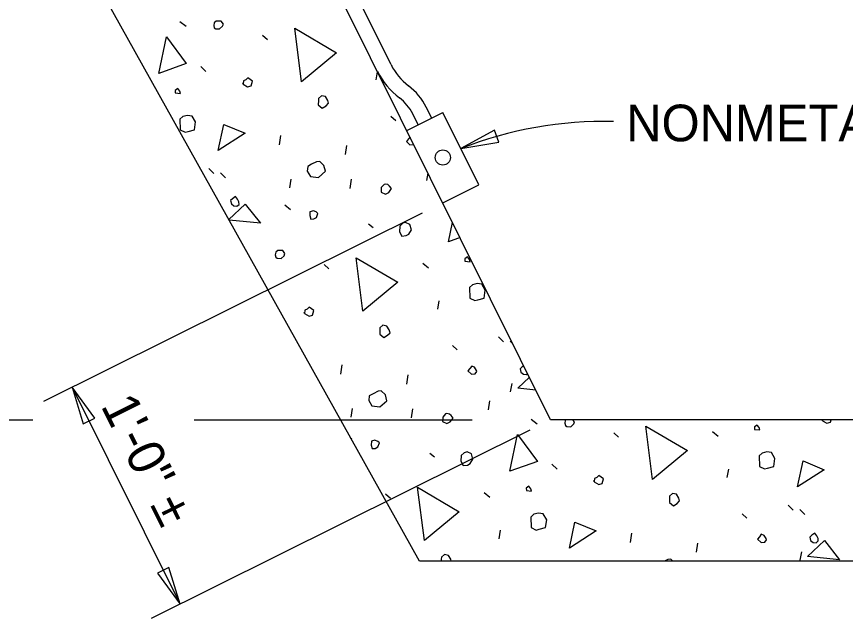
# Model space of a CAD drawing. Extents: x -1660015.2 to -1659984.9, y 2580594.2 to 2580616.7.
# Drawn here: x -1660010.453 to -1660007.032, y 2580605.475 to 2580607.958 of the extents above; entities that cross this region are included whole.
import ezdxf

# ---------------------------------------------------------------- set-up
doc = ezdxf.new("R2010")
doc.units = 0
for name, color, linetype in [('Default', 7, 'Continuous'), ('Miscellaneous', 7, 'Continuous'), ('Miscellaneous3', 7, 'Continuous'), ('PlotBorder_dp', 7, 'Continuous'), ('SheetLines_dp', 7, 'Continuous')]:
    doc.layers.add(name, color=color, linetype=linetype)

msp = doc.modelspace()

# ---------------------------------------------------------------- linework, layer by layer
at = {"layer": 'Default'}
for p, q in [((-1660008.9078, 2580607.7599), (-1660009.0869, 2580608.1201)), ((-1660008.8426, 2580607.4884), (-1660008.6933, 2580607.5627)), ((-1660008.796, 2580607.5116), (-1660008.8184, 2580607.5567)), ((-1660008.74, 2580607.5395), (-1660008.7624, 2580607.5846)), ((-1660008.545, 2580607.2643), (-1660008.6933, 2580607.5627)), ((-1660008.6942, 2580607.1901), (-1660008.545, 2580607.2643))]:
    msp.add_line(p, q, dxfattribs=at)
msp.add_circle((-1660008.6938, 2580607.3764), 0.0313, dxfattribs=at)
for centre, radius, start, end in [((-1660008.6842, 2580607.8717), 0.3125, 206.4422, 232.8307), ((-1660008.6842, 2580607.8717), 0.25, 206.5606, 232.8307), ((-1660008.9863, 2580607.4732), 0.25, 26.4422, 52.8307), ((-1660008.9863, 2580607.4732), 0.1875, 26.4422, 52.8307)]:
    msp.add_arc(centre, radius, start, end, dxfattribs=at)
at = {"layer": 'Miscellaneous'}
for p, q in [((-1660009.7789, 2580607.9381), (-1660009.7531, 2580607.9191)), ((-1660009.4377, 2580607.882), (-1660009.4174, 2580607.8641)), ((-1660009.6927, 2580607.7516), (-1660009.6717, 2580607.7313)), ((-1660008.9689, 2580607.697), (-1660008.9631, 2580607.7307)), ((-1660008.9081, 2580607.5477), (-1660008.8878, 2580607.5298)), ((-1660009.3683, 2580607.4295), (-1660009.3628, 2580607.4672)), ((-1660009.0959, 2580607.3886), (-1660009.0905, 2580607.4263)), ((-1660009.6601, 2580607.3306), (-1660009.6391, 2580607.3104)), ((-1660009.6113, 2580607.3127), (-1660009.5903, 2580607.2924)), ((-1660009.3258, 2580607.252), (-1660009.3198, 2580607.2872)), ((-1660009.0766, 2580607.2489), (-1660009.0711, 2580607.2866)), ((-1660008.7593, 2580607.2821), (-1660008.755, 2580607.3123)), ((-1660009.3459, 2580607.1819), (-1660009.3225, 2580607.1623)), ((-1660009.0013, 2580607.1034), (-1660008.9817, 2580607.088)), ((-1660008.7767, 2580606.941), (-1660008.7533, 2580606.9214)), ((-1660009.1841, 2580606.9354), (-1660009.1638, 2580606.9175)), ((-1660008.7152, 2580606.7504), (-1660008.7092, 2580606.7857)), ((-1660008.4647, 2580606.6364), (-1660008.4437, 2580606.6161)), ((-1660008.6545, 2580606.601), (-1660008.6342, 2580606.5832)), ((-1660008.4159, 2580606.6184), (-1660008.4044, 2580606.6073)), ((-1660009.1146, 2580606.4829), (-1660009.1092, 2580606.5206)), ((-1660008.8422, 2580606.442), (-1660008.8368, 2580606.4797)), ((-1660008.4142, 2580606.4092), (-1660008.4081, 2580606.4445)), ((-1660008.5057, 2580606.3355), (-1660008.5003, 2580606.3732)), ((-1660009.0722, 2580606.3054), (-1660009.0661, 2580606.3406)), ((-1660008.8229, 2580606.3023), (-1660008.8175, 2580606.34)), ((-1660008.3298, 2580606.2972), (-1660008.304, 2580606.2783)), ((-1660007.9887, 2580606.2411), (-1660007.9683, 2580606.2233)), ((-1660007.5812, 2580606.2468), (-1660007.5579, 2580606.2271)), ((-1660009.0748, 2580606.2206), (-1660009.0689, 2580606.2157)), ((-1660008.7477, 2580606.1568), (-1660008.728, 2580606.1414)), ((-1660008.2436, 2580606.1107), (-1660008.2226, 2580606.0904)), ((-1660007.5198, 2580606.0562), (-1660007.5137, 2580606.0914)), ((-1660008.9304, 2580605.9888), (-1660008.9101, 2580605.9709)), ((-1660008.523, 2580605.9944), (-1660008.4996, 2580605.9748)), ((-1660007.2693, 2580605.9421), (-1660007.2483, 2580605.9219)), ((-1660007.2204, 2580605.9241), (-1660007.1995, 2580605.9039)), ((-1660007.4591, 2580605.9068), (-1660007.4388, 2580605.8889)), ((-1660008.4616, 2580605.8038), (-1660008.4555, 2580605.8391)), ((-1660007.9192, 2580605.7887), (-1660007.9138, 2580605.8264)), ((-1660007.6468, 2580605.7478), (-1660007.6414, 2580605.7855)), ((-1660007.2187, 2580605.715), (-1660007.2127, 2580605.7502))]:
    msp.add_line(p, q, dxfattribs=at)
for points in [[(-1660009.6371, 2580607.9114), (-1660009.631, 2580607.9078), (-1660009.6152, 2580607.9069), (-1660009.6027, 2580607.918), (-1660009.5998, 2580607.9266), (-1660009.6085, 2580607.9398), (-1660009.6291, 2580607.9394), (-1660009.6375, 2580607.932), (-1660009.6397, 2580607.921), (-1660009.6371, 2580607.9114)], [(-1660009.2774, 2580607.6894), (-1660009.3054, 2580607.9097), (-1660009.1333, 2580607.8083), (-1660009.2774, 2580607.6894)], [(-1660009.8662, 2580607.7232), (-1660009.8342, 2580607.8741), (-1660009.7529, 2580607.7639), (-1660009.8662, 2580607.7232)], [(-1660009.518, 2580607.6793), (-1660009.4996, 2580607.6687), (-1660009.4851, 2580607.6726), (-1660009.48, 2580607.6921), (-1660009.499, 2580607.7051), (-1660009.5074, 2580607.6977), (-1660009.5164, 2580607.6927), (-1660009.518, 2580607.6793), (-1660009.5193, 2580607.6841)], [(-1660009.7982, 2580607.6431), (-1660009.7769, 2580607.641), (-1660009.7795, 2580607.6506), (-1660009.7876, 2580607.6614), (-1660009.7983, 2580607.6534), (-1660009.7982, 2580607.6431)], [(-1660009.2076, 2580607.6124), (-1660009.2079, 2580607.5942), (-1660009.1913, 2580607.5805), (-1660009.1757, 2580607.5898), (-1660009.1655, 2580607.6003), (-1660009.1688, 2580607.6124), (-1660009.1781, 2580607.628), (-1660009.1946, 2580607.6314), (-1660009.2071, 2580607.6202), (-1660009.2076, 2580607.6124)], [(-1660009.7794, 2580607.5342), (-1660009.778, 2580607.4906), (-1660009.7572, 2580607.4806), (-1660009.7452, 2580607.4838), (-1660009.7186, 2580607.491), (-1660009.7143, 2580607.5232), (-1660009.7286, 2580607.5478), (-1660009.7475, 2580607.5505), (-1660009.7668, 2580607.5453), (-1660009.7794, 2580607.5342)], [(-1660009.6207, 2580607.4059), (-1660009.5977, 2580607.513), (-1660009.5103, 2580607.4769), (-1660009.6207, 2580607.4059)], [(-1660008.8293, 2580607.4618), (-1660008.8362, 2580607.453), (-1660008.8439, 2580607.4432)], [(-1660008.8439, 2580607.4432), (-1660008.8297, 2580607.4289), (-1660008.8146, 2580607.4304), (-1660008.8141, 2580607.4311)], [(-1660009.2536, 2580607.3205), (-1660009.2399, 2580607.2983), (-1660009.2077, 2580607.294), (-1660009.1784, 2580607.3199), (-1660009.1849, 2580607.3441), (-1660009.2021, 2580607.3602), (-1660009.2149, 2580607.3594), (-1660009.2353, 2580607.3487), (-1660009.2509, 2580607.3393), (-1660009.2536, 2580607.3205)], [(-1660008.9481, 2580607.2523), (-1660008.9484, 2580607.2341), (-1660008.9306, 2580607.2259), (-1660008.9168, 2580607.2322), (-1660008.9055, 2580607.2481), (-1660008.9136, 2580607.2589), (-1660008.9204, 2580607.2649), (-1660008.9313, 2580607.2671), (-1660008.9362, 2580607.2658), (-1660008.9481, 2580607.2523)], [(-1660009.5667, 2580607.1848), (-1660009.5569, 2580607.1771), (-1660009.5435, 2580607.1755), (-1660009.5351, 2580607.183), (-1660009.5353, 2580607.1933), (-1660009.5409, 2580607.2047), (-1660009.549, 2580607.2155), (-1660009.5622, 2580607.2068), (-1660009.5706, 2580607.1993), (-1660009.5667, 2580607.1848)], [(-1660009.5775, 2580607.1215), (-1660009.5097, 2580607.1846), (-1660009.4471, 2580607.1056), (-1660009.5759, 2580607.1187)], [(-1660009.2433, 2580607.1369), (-1660009.2394, 2580607.1224), (-1660009.2267, 2580607.1233), (-1660009.2152, 2580607.1289), (-1660009.2095, 2580607.146), (-1660009.2162, 2580607.1519), (-1660009.2278, 2580607.1566), (-1660009.2423, 2580607.1527), (-1660009.2433, 2580607.1369)], [(-1660008.872, 2580607.094), (-1660008.8734, 2580607.0704), (-1660008.8634, 2580607.0524), (-1660008.8459, 2580607.0545), (-1660008.8344, 2580607.0601), (-1660008.8238, 2580607.0785), (-1660008.8297, 2580607.1002), (-1660008.8474, 2580607.1084), (-1660008.8595, 2580607.1052), (-1660008.872, 2580607.094)], [(-1660008.6708, 2580607.0289), (-1660008.6538, 2580607.1089)], [(-1660008.6226, 2580607.0462), (-1660008.6708, 2580607.0289)], [(-1660009.3835, 2580606.9648), (-1660009.3774, 2580606.9612), (-1660009.3616, 2580606.9603), (-1660009.349, 2580606.9714), (-1660009.3461, 2580606.9799), (-1660009.3548, 2580606.9931), (-1660009.3755, 2580606.9928), (-1660009.3838, 2580606.9854), (-1660009.3861, 2580606.9744), (-1660009.3835, 2580606.9648)], [(-1660009.0238, 2580606.7428), (-1660009.0517, 2580606.9631), (-1660008.8796, 2580606.8617), (-1660009.0238, 2580606.7428)], [(-1660008.6027, 2580606.9488), (-1660008.5815, 2580606.9467), (-1660008.5841, 2580606.9564), (-1660008.5921, 2580606.9672), (-1660008.6029, 2580606.9591), (-1660008.6027, 2580606.9488)], [(-1660008.5839, 2580606.84), (-1660008.5826, 2580606.7963), (-1660008.5618, 2580606.7864), (-1660008.5497, 2580606.7896), (-1660008.5232, 2580606.7967), (-1660008.5189, 2580606.8289), (-1660008.5332, 2580606.8535), (-1660008.5521, 2580606.8563), (-1660008.5714, 2580606.8511), (-1660008.5839, 2580606.84)], [(-1660009.2644, 2580606.7327), (-1660009.246, 2580606.7221), (-1660009.2315, 2580606.726), (-1660009.2264, 2580606.7455), (-1660009.2454, 2580606.7585), (-1660009.2537, 2580606.7511), (-1660009.2628, 2580606.7461), (-1660009.2644, 2580606.7327), (-1660009.2656, 2580606.7375)], [(-1660008.954, 2580606.6657), (-1660008.9543, 2580606.6476), (-1660008.9376, 2580606.6339), (-1660008.922, 2580606.6432), (-1660008.9119, 2580606.6537), (-1660008.9151, 2580606.6658), (-1660008.9245, 2580606.6814), (-1660008.9409, 2580606.6848), (-1660008.9535, 2580606.6736), (-1660008.954, 2580606.6657)], [(-1660008.5903, 2580606.4966), (-1660008.5761, 2580606.4823), (-1660008.561, 2580606.4838), (-1660008.5532, 2580606.4936), (-1660008.5545, 2580606.4984), (-1660008.5632, 2580606.5116), (-1660008.5748, 2580606.5163), (-1660008.5826, 2580606.5064), (-1660008.5903, 2580606.4966)], [(-1660008.3596, 2580606.5172), (-1660008.3668, 2580606.5125), (-1660008.3751, 2580606.5051), (-1660008.3713, 2580606.4906)], [(-1660008.3847, 2580606.4249), (-1660008.3361, 2580606.47)], [(-1660008.3713, 2580606.4906), (-1660008.3614, 2580606.4829), (-1660008.3481, 2580606.4813), (-1660008.3436, 2580606.4852)], [(-1660009, 2580606.3739), (-1660008.9863, 2580606.3517), (-1660008.9541, 2580606.3474), (-1660008.9248, 2580606.3733), (-1660008.9312, 2580606.3975), (-1660008.9485, 2580606.4136), (-1660008.9612, 2580606.4127), (-1660008.9817, 2580606.4021), (-1660008.9973, 2580606.3927), (-1660009, 2580606.3739)], [(-1660008.3099, 2580606.4173), (-1660008.3847, 2580606.4249)], [(-1660008.6944, 2580606.3057), (-1660008.6947, 2580606.2875), (-1660008.677, 2580606.2793), (-1660008.6631, 2580606.2856), (-1660008.6519, 2580606.3015), (-1660008.66, 2580606.3123), (-1660008.6667, 2580606.3182), (-1660008.6777, 2580606.3205), (-1660008.6825, 2580606.3192), (-1660008.6944, 2580606.3057)], [(-1660008.1844, 2580606.2947), (-1660008.1884, 2580606.2911), (-1660008.1906, 2580606.2802), (-1660008.1881, 2580606.2705)], [(-1660008.1881, 2580606.2705), (-1660008.1819, 2580606.267), (-1660008.1662, 2580606.266), (-1660008.1536, 2580606.2772), (-1660008.1507, 2580606.2857), (-1660008.1567, 2580606.2947)], [(-1660007.1267, 2580606.2947), (-1660007.1272, 2580606.2908), (-1660007.1282, 2580606.2947)], [(-1660007.1272, 2580606.2908), (-1660007.1088, 2580606.2802), (-1660007.0943, 2580606.2841), (-1660007.0915, 2580606.2947)], [(-1660007.8284, 2580606.0485), (-1660007.8563, 2580606.2688), (-1660007.6842, 2580606.1674), (-1660007.8284, 2580606.0485)], [(-1660007.4073, 2580606.2545), (-1660007.3861, 2580606.2525), (-1660007.3887, 2580606.2621), (-1660007.3967, 2580606.2729), (-1660007.4075, 2580606.2648), (-1660007.4073, 2580606.2545)], [(-1660008.4172, 2580606.0823), (-1660008.3851, 2580606.2332), (-1660008.3038, 2580606.123), (-1660008.4172, 2580606.0823)], [(-1660008.9896, 2580606.1903), (-1660008.9857, 2580606.1758), (-1660008.973, 2580606.1766), (-1660008.9616, 2580606.1823), (-1660008.9558, 2580606.1994), (-1660008.9626, 2580606.2053), (-1660008.9742, 2580606.21), (-1660008.9887, 2580606.2061), (-1660008.9896, 2580606.1903)], [(-1660008.6184, 2580606.1474), (-1660008.6198, 2580606.1238), (-1660008.6098, 2580606.1057), (-1660008.5922, 2580606.1079), (-1660008.5808, 2580606.1135), (-1660008.5702, 2580606.1319), (-1660008.576, 2580606.1536), (-1660008.5937, 2580606.1618), (-1660008.6058, 2580606.1586), (-1660008.6184, 2580606.1474)], [(-1660007.3885, 2580606.1457), (-1660007.3872, 2580606.1021), (-1660007.3664, 2580606.0921), (-1660007.3543, 2580606.0953), (-1660007.3277, 2580606.1024), (-1660007.3234, 2580606.1347), (-1660007.3378, 2580606.1593), (-1660007.3566, 2580606.162), (-1660007.376, 2580606.1568), (-1660007.3885, 2580606.1457)], [(-1660007.2299, 2580606.0174), (-1660007.2068, 2580606.1245), (-1660007.1195, 2580606.0884), (-1660007.2299, 2580606.0174)], [(-1660008.0689, 2580606.0384), (-1660008.0506, 2580606.0278), (-1660008.0361, 2580606.0317), (-1660008.0309, 2580606.0512), (-1660008.05, 2580606.0642), (-1660008.0583, 2580606.0568), (-1660008.0673, 2580606.0518), (-1660008.0689, 2580606.0384), (-1660008.0702, 2580606.0433)], [(-1660008.3491, 2580606.0022), (-1660008.3278, 2580606.0001), (-1660008.3304, 2580606.0098), (-1660008.3385, 2580606.0206), (-1660008.3493, 2580606.0125), (-1660008.3491, 2580606.0022)], [(-1660008.7701, 2580605.7962), (-1660008.7981, 2580606.0165), (-1660008.626, 2580605.9151), (-1660008.7701, 2580605.7962)], [(-1660007.7585, 2580605.9715), (-1660007.7588, 2580605.9533), (-1660007.7422, 2580605.9396), (-1660007.7266, 2580605.949), (-1660007.7165, 2580605.9595), (-1660007.7197, 2580605.9715), (-1660007.7291, 2580605.9871), (-1660007.7455, 2580605.9905), (-1660007.7581, 2580605.9794), (-1660007.7585, 2580605.9715)], [(-1660008.3303, 2580605.8933), (-1660008.3289, 2580605.8497), (-1660008.3082, 2580605.8397), (-1660008.2961, 2580605.843), (-1660008.2695, 2580605.8501), (-1660008.2652, 2580605.8823), (-1660008.2796, 2580605.9069), (-1660008.2984, 2580605.9096), (-1660008.3177, 2580605.9045), (-1660008.3303, 2580605.8933)], [(-1660008.1717, 2580605.765), (-1660008.1486, 2580605.8721), (-1660008.0613, 2580605.836), (-1660008.1717, 2580605.765)], [(-1660007.3949, 2580605.8024), (-1660007.3807, 2580605.788), (-1660007.3655, 2580605.7895), (-1660007.3578, 2580605.7993), (-1660007.3591, 2580605.8042), (-1660007.3678, 2580605.8174), (-1660007.3794, 2580605.822), (-1660007.3871, 2580605.8122), (-1660007.3949, 2580605.8024)], [(-1660007.1758, 2580605.7963), (-1660007.166, 2580605.7886), (-1660007.1526, 2580605.787), (-1660007.1443, 2580605.7944), (-1660007.1445, 2580605.8047), (-1660007.1501, 2580605.8162), (-1660007.1582, 2580605.827), (-1660007.1714, 2580605.8182), (-1660007.1797, 2580605.8108), (-1660007.1758, 2580605.7963)], [(-1660007.1893, 2580605.7306), (-1660007.1188, 2580605.7961), (-1660007.0563, 2580605.7171), (-1660007.1893, 2580605.7306)], [(-1660008.7003, 2580605.7191), (-1660008.7004, 2580605.7114)], [(-1660008.6594, 2580605.7114), (-1660008.6615, 2580605.7192), (-1660008.6709, 2580605.7348), (-1660008.6873, 2580605.7382), (-1660008.6998, 2580605.727), (-1660008.7003, 2580605.7191)], [(-1660007.7446, 2580605.7114), (-1660007.7531, 2580605.7193), (-1660007.7658, 2580605.7185), (-1660007.7793, 2580605.7114)]]:
    msp.add_lwpolyline(points, dxfattribs=at)
at = {"layer": 'Miscellaneous3'}
for p, q in [((-1660008.7906, 2580605.7114), (-1660012.2404, 2580611.8935)), ((-1660008.2489, 2580606.2947), (-1660009.4781, 2580608.7663)), ((-1660004.5045, 2580606.2947), (-1660008.2489, 2580606.2947)), ((-1660004.5045, 2580605.7114), (-1660008.7906, 2580605.7114))]:
    msp.add_line(p, q, dxfattribs=at)
at = {"layer": 'SheetLines_dp'}
for p, q in [((-1660008.7796, 2580607.1476), (-1660010.3426, 2580606.3703)), ((-1660010.224, 2580606.4293), (-1660009.7787, 2580605.5339)), ((-1660013.0517, 2580606.2947), (-1660010.3859, 2580606.2947)), ((-1660009.72, 2580606.2947), (-1660008.5722, 2580606.2947)), ((-1660008.3343, 2580606.2522), (-1660009.8973, 2580605.4749))]:
    msp.add_line(p, q, dxfattribs=at)
for points in [[(-1660008.6191, 2580607.4134), (-1660008.4629, 2580607.4394), (-1660008.4801, 2580607.4895)], [(-1660010.224, 2580606.4292), (-1660010.1782, 2580606.2776), (-1660010.1308, 2580606.3011)], [(-1660009.7787, 2580605.5339), (-1660009.8246, 2580605.6855), (-1660009.8719, 2580605.6619)]]:
    msp.add_lwpolyline(points, close=True, dxfattribs=at)
msp.add_arc((-1660008.0297, 2580605.9195), 1.606, 88.5611, 111.5329, dxfattribs=at)

# ---------------------------------------------------------------- texts
at = {"layer": 'PlotBorder_dp'}
msp.add_text('NONMETALLIC OUTLET BOX', height=0.1512, dxfattribs=at).set_placement((-1660007.9373, 2580607.4435))
msp.add_text('1\'-0" ±', height=0.1512, rotation=296.4422, dxfattribs=at).set_placement((-1660010.1072, 2580606.3529))

doc.saveas('drawing.dxf')
